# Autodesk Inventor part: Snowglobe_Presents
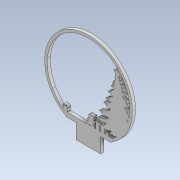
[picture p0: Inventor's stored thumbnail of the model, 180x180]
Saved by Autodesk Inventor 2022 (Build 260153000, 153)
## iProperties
Created: 2021-12
Part Number: Snowglobe_Presents
Material: Generic
Document SubType Name: Modeling
Designer: allis
Density: 1 g/cm^3
Appearance: Default
Author: allis
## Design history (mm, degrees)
sketch "Sketch2"
  geometry: L1 (26.796, -80.826)-(26.535, -80.542); L2 (26.535, -80.542)-(26.233, -80.329); L3 (26.233, -80.329)-(25.851, -80.248); L4 (25.851, -80.248)-(26.068, -80.604); L5 (26.068, -80.604)-(26.409, -80.753); L6 (26.409, -80.753)-(26.796, -80.826); L7 (27.591, -80.765)-(27.624, -80.797); L8 (27.624, -80.797)-(27.656, -80.83); L9 (27.656, -80.83)-(27.689, -80.863); L10 (27.689, -80.863)-(28.01, -80.63); L11 (28.01, -80.63)-(28.406, -80.482); L12 (28.406, -80.482)-(28.563, -80.07); L13 (28.563, -80.07)-(28.536, -80.04); L14 (28.536, -80.04)-(28.509, -80.01); L15 (28.509, -80.01)-(28.483, -79.979); L16 (28.483, -79.979)-(28.185, -80.241); L17 (28.185, -80.241)-(27.888, -80.503); L18 (27.888, -80.503)-(27.591, -80.765); L19 (50.653, -85.561)-(51.562, -85.561); L20 (51.562, -85.561)-(52.458, -85.561); L21 (52.458, -85.561)-(53.446, -85.561); L22 (53.446, -85.561)-(53.002, -85.257); L23 (53.002, -85.257)-(52.617, -85.116); L24 (52.617, -85.116)-(52.174, -85.214); L25 (52.174, -85.214)-(51.67, -85.325); L26 (51.67, -85.325)-(51.168, -85.443); L27 (51.168, -85.443)-(50.653, -85.561); L28 (91.991, -59.522)-(92.089, -58.929); L29 (92.089, -58.929)-(92.171, -58.443); L30 (92.171, -58.443)-(92.255, -57.934); L31 (92.255, -57.934)-(91.857, -58.033); L32 (91.857, -58.033)-(91.524, -58.116); L33 (91.524, -58.116)-(91.158, -58.208); L34 (91.158, -58.208)-(91.266, -58.738); L35 (91.266, -58.738)-(91.602, -59.079); L36 (91.602, -59.079)-(91.991, -59.522); L37 (89.526, -62.089)-(89.338, -62.218); L38 (89.338, -62.218)-(89.372, -62.366); L39 (89.372, -62.366)-(89.506, -62.51); L40 (89.506, -62.51)-(89.918, -62.954); L41 (89.918, -62.954)-(90.398, -63.308); L42 (90.398, -63.308)-(90.975, -63.632); L43 (90.975, -63.632)-(91.071, -63.289); L44 (91.071, -63.289)-(91.154, -62.992); L45 (91.154, -62.992)-(91.215, -62.773); L46 (91.215, -62.773)-(90.614, -62.53); L47 (90.614, -62.53)-(90.087, -62.317); L48 (90.087, -62.317)-(89.526, -62.089); L49 (62.517, -78.614)-(61.699, -77.836); L50 (61.699, -77.836)-(60.915, -77.007); L51 (60.915, -77.007)-(59.79, -76.623); L52 (59.79, -76.623)-(59.949, -76.943); L53 (59.949, -76.943)-(60.114, -77.267); L54 (60.114, -77.267)-(60.372, -77.478); L55 (60.372, -77.478)-(61.002, -77.994); L56 (61.002, -77.994)-(61.731, -78.354); L57 (61.731, -78.354)-(62.517, -78.614); L58 (65.931, -76.164)-(65.893, -76.149); L59 (65.893, -76.149)-(65.855, -76.134); L60 (65.855, -76.134)-(65.816, -76.119); L61 (65.816, -76.119)-(64.842, -76.75); L62 (64.842, -76.75)-(64.16, -77.65); L63 (64.16, -77.65)-(63.545, -78.616); L64 (63.545, -78.616)-(64.018, -78.327)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; 1 further point
  constraints: 30 end point, 417 other
extrude "Extrusion1" new body sketch "Sketch2" distance "d0" = 3.175; taper "d1" = 0 deg
body "Solid1"
